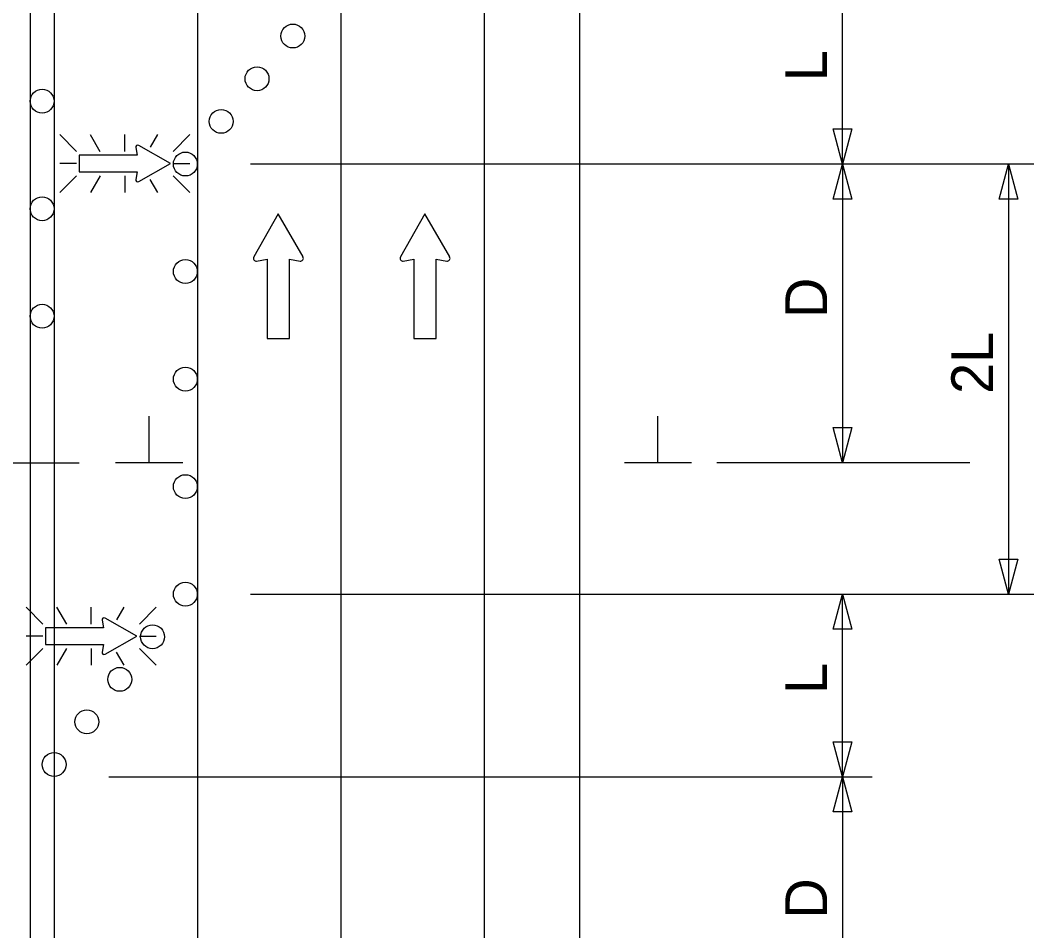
# Model space of a CAD drawing. Extents: x 16733 to 18475, y 7003 to 8205.
# Drawn here: x 16997.7 to 17167.4, y 7640.4 to 7792.8 of the extents above; entities that cross this region are included whole.
import ezdxf

# ---------------------------------------------------------------- set-up
doc = ezdxf.new("R2010")
doc.units = 0
for name, color, linetype in [('ALI_LEGAL_EX', 7, 'Continuous'), ('MT_SCRATCH_LEVEL_E', 7, 'Continuous'), ('PAVT_EDGE_EX', 7, 'Continuous'), ('TRAFFIC_SIGNS_PR', 7, 'Continuous'), ('TYPICAL_TEXT_DIMEN_PR', 7, 'Continuous')]:
    doc.layers.add(name, color=color, linetype=linetype)

msp = doc.modelspace()

# ---------------------------------------------------------------- linework, layer by layer
at = {"layer": 'ALI_LEGAL_EX'}
for p, q in [((17027.37, 8191.42), (17027.37, 7362.23)), ((17051.37, 8191.42), (17051.37, 7362.23)), ((17051.37, 8191.42), (17051.37, 7362.23))]:
    msp.add_line(p, q, dxfattribs=at)
for points in [[(17027.37, 7791.42), (17027.37, 7766.42)], [(17051.37, 7791.42), (17051.37, 7766.42)], [(17027.37, 7691.42), (17027.37, 7666.42)], [(17051.37, 7691.42), (17051.37, 7666.42)]]:
    msp.add_lwpolyline(points, dxfattribs=at)
at = {"layer": 'MT_SCRATCH_LEVEL_E'}
for p, q in [((17040.91, 7760.38), (17036.8, 7753.14)), ((17040.91, 7760.38), (17036.8, 7753.14)), ((17045.06, 7753.14), (17040.91, 7760.38)), ((17045.06, 7753.14), (17040.91, 7760.38)), ((17065.47, 7760.38), (17061.36, 7753.14)), ((17065.47, 7760.38), (17061.36, 7753.14)), ((17069.62, 7753.14), (17065.47, 7760.38)), ((17069.62, 7753.14), (17065.47, 7760.38)), ((17037.28, 7752.45), (17039.06, 7752.77)), ((17037.28, 7752.45), (17039.06, 7752.77)), ((17039.06, 7752.77), (17039.06, 7739.51)), ((17039.06, 7752.77), (17039.06, 7739.51)), ((17042.8, 7739.51), (17042.8, 7752.77)), ((17042.8, 7752.77), (17044.58, 7752.45)), ((17042.8, 7739.51), (17042.8, 7752.77)), ((17042.8, 7752.77), (17044.58, 7752.45)), ((17061.84, 7752.45), (17063.62, 7752.77)), ((17061.84, 7752.45), (17063.62, 7752.77)), ((17063.62, 7752.77), (17063.62, 7739.51)), ((17063.62, 7752.77), (17063.62, 7739.51)), ((17067.36, 7739.51), (17067.36, 7752.77)), ((17067.36, 7752.77), (17069.14, 7752.45)), ((17067.36, 7739.51), (17067.36, 7752.77)), ((17067.36, 7752.77), (17069.14, 7752.45)), ((17039.06, 7739.51), (17042.8, 7739.51)), ((17039.06, 7739.51), (17042.8, 7739.51)), ((17063.62, 7739.51), (17067.36, 7739.51)), ((17063.62, 7739.51), (17067.36, 7739.51))]:
    msp.add_line(p, q, dxfattribs=at)
for centre, start, end in [((17037.21, 7752.91), 150.4248, 279.9638), ((17037.21, 7752.91), 150.4248, 279.9638), ((17044.65, 7752.91), 260.0362, 29.7731), ((17044.65, 7752.91), 260.0362, 29.7731), ((17061.77, 7752.91), 150.4248, 279.9638), ((17061.77, 7752.91), 150.4248, 279.9638), ((17069.21, 7752.91), 260.0362, 29.7731), ((17069.21, 7752.91), 260.0362, 29.7731)]:
    msp.add_arc(centre, 0.463, start, end, dxfattribs=at)
at = {"layer": 'PAVT_EDGE_EX'}
for p, q in [((16999.37, 8191.42), (16999.37, 7362.23)), ((17003.37, 8191.42), (17003.37, 7362.23)), ((17075.37, 8191.42), (17075.37, 7362.23)), ((17091.37, 8191.42), (17091.37, 7362.23))]:
    msp.add_line(p, q, dxfattribs=at)
at = {"layer": 'TRAFFIC_SIGNS_PR'}
for p, q in [((17007.14, 7770.81), (17004.32, 7773.63)), ((17009.44, 7773.63), (17011.06, 7770.81)), ((17015.22, 7770.81), (17015.22, 7773.63)), ((17020.69, 7773.63), (17019.49, 7771.53)), ((17026.13, 7773.62), (17023.31, 7770.81)), ((17007.14, 7768.77), (17004.32, 7768.77)), ((17023.31, 7768.77), (17026.13, 7768.77)), ((17007.14, 7766.74), (17004.32, 7763.92)), ((17011.09, 7766.74), (17009.46, 7763.92)), ((17015.22, 7766.74), (17015.22, 7763.92)), ((17019.41, 7766.11), (17020.67, 7763.92)), ((17026.13, 7763.92), (17023.31, 7766.74)), ((17001.51, 7691.69), (16998.68, 7694.51)), ((17003.8, 7694.51), (17005.43, 7691.69)), ((17009.59, 7691.69), (17009.59, 7694.51)), ((17015.06, 7694.51), (17013.85, 7692.42)), ((17020.49, 7694.51), (17017.67, 7691.69)), ((17001.51, 7689.66), (16998.68, 7689.66)), ((17017.67, 7689.66), (17020.49, 7689.66)), ((17001.51, 7687.63), (16998.68, 7684.81)), ((17005.46, 7687.63), (17003.83, 7684.81)), ((17009.59, 7687.63), (17009.59, 7684.81)), ((17020.49, 7684.81), (17017.67, 7687.63)), ((17013.77, 7686.99), (17015.03, 7684.81))]:
    msp.add_line(p, q, dxfattribs=at)
for points in [[(17017.05, 7771.46), (17017.28, 7770.16), (17007.56, 7770.16), (17007.56, 7767.42), (17017.28, 7767.42), (17017.05, 7766.11)], [(17017.55, 7765.76), (17022.86, 7768.77), (17017.55, 7771.82)], [(17011.42, 7692.34), (17011.65, 7691.04), (17001.92, 7691.04), (17001.92, 7688.3), (17011.65, 7688.3), (17011.42, 7687)], [(17011.92, 7686.64), (17017.23, 7689.66), (17011.92, 7692.7)]]:
    msp.add_lwpolyline(points, dxfattribs=at)
for centre in [(17043.36, 7790.13), (17037.36, 7782.98), (17001.37, 7779.22), (17031.36, 7775.84), (17025.36, 7768.7), (17025.36, 7768.7), (17001.37, 7761.22), (17025.36, 7750.7), (17001.37, 7743.22), (17025.36, 7732.7), (17025.36, 7714.7), (17025.36, 7696.7), (17019.87, 7689.57), (17014.37, 7682.44), (17008.87, 7675.32), (17003.38, 7668.19)]:
    msp.add_circle(centre, 2, dxfattribs=at)
for centre, start, end in [((17017.39, 7771.51), 61.4833, 189.9593), ((17017.39, 7766.06), 170.7308, 298.8916), ((17011.75, 7692.4), 61.4833, 189.9593), ((17011.75, 7686.94), 170.7308, 298.8916)]:
    msp.add_arc(centre, 0.341, start, end, dxfattribs=at)
at = {"layer": 'TYPICAL_TEXT_DIMEN_PR'}
for p, q in [((17135.37, 7768.7), (17135.37, 7799.27)), ((17135.37, 7768.7), (17133.8, 7774.57)), ((17133.8, 7774.57), (17135.37, 7774.57)), ((17135.37, 7774.57), (17136.94, 7774.57)), ((17136.94, 7774.57), (17135.37, 7768.7)), ((17167.41, 7768.7), (17036.26, 7768.7)), ((17133.8, 7762.84), (17135.37, 7768.7)), ((17135.37, 7768.7), (17135.37, 7718.7)), ((17135.37, 7768.7), (17136.94, 7762.84)), ((17161.6, 7762.84), (17163.17, 7768.7)), ((17163.17, 7768.7), (17164.74, 7762.84)), ((17163.17, 7768.7), (17163.17, 7696.7)), ((17135.37, 7762.84), (17133.8, 7762.84)), ((17136.94, 7762.84), (17135.37, 7762.84)), ((17163.17, 7762.84), (17161.6, 7762.84)), ((17164.74, 7762.84), (17163.17, 7762.84)), ((17019.29, 7718.7), (17019.29, 7726.49)), ((17104.49, 7718.7), (17104.49, 7726.49)), ((17135.37, 7718.7), (17133.8, 7724.57)), ((17133.8, 7724.57), (17135.37, 7724.57)), ((17135.37, 7724.57), (17136.94, 7724.57)), ((17136.94, 7724.57), (17135.37, 7718.7)), ((17163.17, 7723.57), (17163.17, 7719.8)), ((16859.36, 7718.7), (17007.56, 7718.7)), ((17024.92, 7718.7), (17013.67, 7718.7)), ((17110.12, 7718.7), (17098.87, 7718.7)), ((17156.72, 7718.7), (17114.37, 7718.7)), ((17163.17, 7696.7), (17161.6, 7702.57)), ((17161.6, 7702.57), (17163.17, 7702.57)), ((17163.17, 7702.57), (17164.74, 7702.57)), ((17164.74, 7702.57), (17163.17, 7696.7)), ((17036.26, 7696.7), (17167.41, 7696.7)), ((17133.8, 7690.84), (17135.37, 7696.7)), ((17135.37, 7666.14), (17135.37, 7696.7)), ((17135.37, 7696.7), (17136.94, 7690.84)), ((17135.37, 7690.84), (17133.8, 7690.84)), ((17136.94, 7690.84), (17135.37, 7690.84)), ((17135.37, 7666.14), (17133.8, 7672)), ((17133.8, 7672), (17135.37, 7672)), ((17135.37, 7672), (17136.94, 7672)), ((17136.94, 7672), (17135.37, 7666.14)), ((17012.53, 7666.14), (17140.37, 7666.14)), ((17133.8, 7660.28), (17135.37, 7666.14)), ((17133.8, 7660.28), (17135.37, 7666.14)), ((17135.37, 7666.14), (17135.37, 7616.14)), ((17135.37, 7666.14), (17136.94, 7660.28)), ((17135.37, 7666.14), (17136.94, 7660.28)), ((17135.37, 7660.28), (17133.8, 7660.28)), ((17135.37, 7660.28), (17133.8, 7660.28)), ((17136.94, 7660.28), (17135.37, 7660.28)), ((17136.94, 7660.28), (17135.37, 7660.28))]:
    msp.add_line(p, q, dxfattribs=at)

# ---------------------------------------------------------------- texts
for s, p in [('L', (17132.81, 7782.56)), ('D', (17132.81, 7742.92)), ('2L', (17160.61, 7730.21)), ('L', (17132.81, 7680)), ('D', (17132.81, 7642.37))]:
    msp.add_text(s, height=7, rotation=90, dxfattribs=at).set_placement(p)

doc.saveas('drawing.dxf')
